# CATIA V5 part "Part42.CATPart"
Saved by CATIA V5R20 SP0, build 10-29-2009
Part number: 9AE052430-2
Revision: ANY
Definition: UNKNOWN
Nomenclature: 9AE052430-2
Source: Unknown
Bounding box of the stored display mesh (mm): x -16.827 to 16.827, y 0 to 44, z -17 to 17
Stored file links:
  C:\Users\Utente\Desktop\IO LAVORO\3D X SITO CF\CUMSA\3D files AE\AE 082430\Part42.CATPart
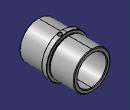
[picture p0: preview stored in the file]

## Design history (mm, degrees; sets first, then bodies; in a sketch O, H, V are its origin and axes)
Body1 "Cortar-Extruir1" (main body)
  Solid1: solid without history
